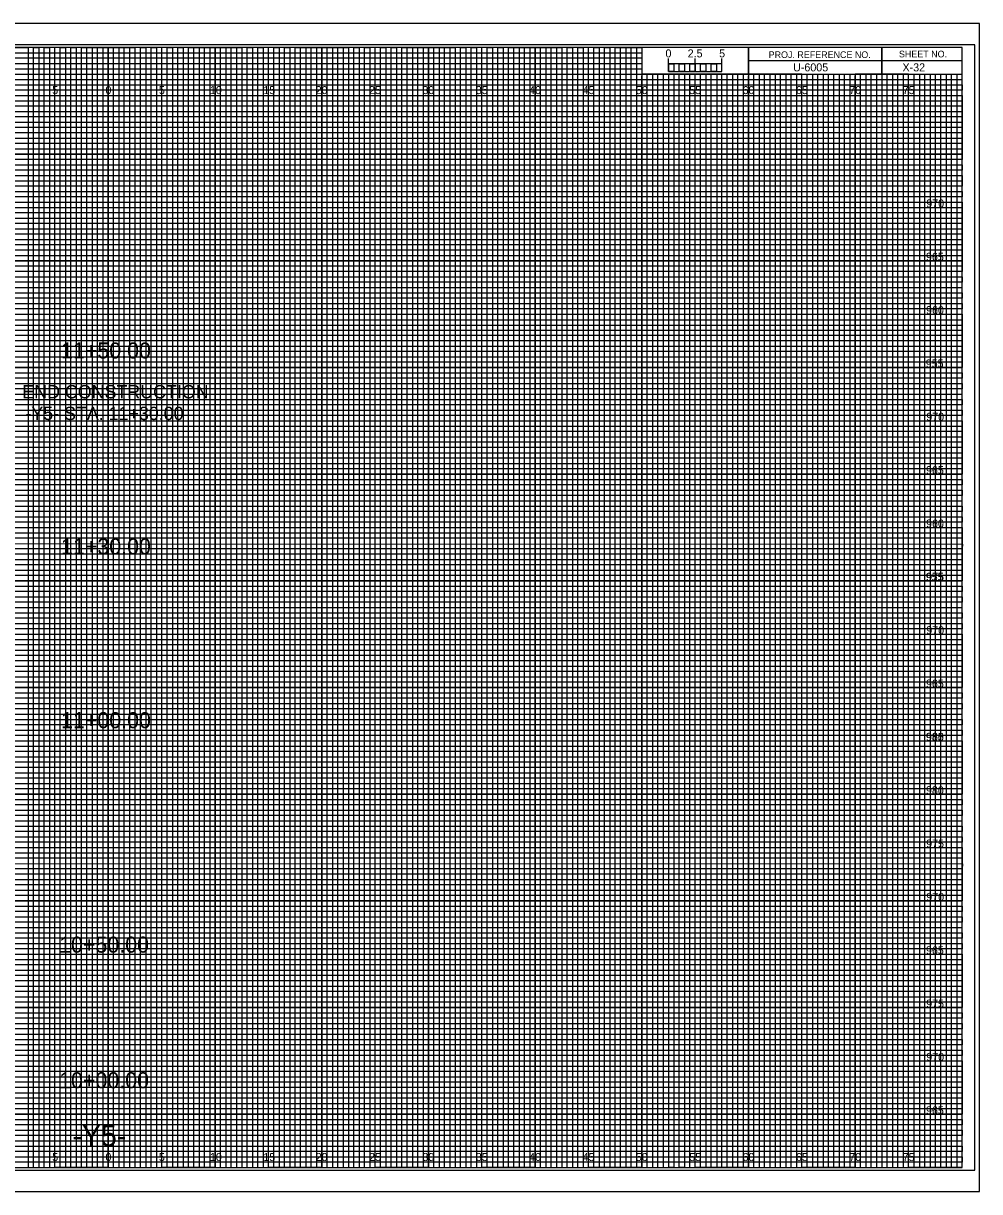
# Model space of a CAD drawing. Extents: x -7 to 162, y -2 to 107.
# Drawn here: x 72 to 161.7, y -2.3 to 107.3 of the extents above; entities that cross this region are included whole.
import ezdxf

# ---------------------------------------------------------------- set-up
doc = ezdxf.new("R2010")
doc.units = 0
for name, color, linetype in [('Prop XS Alignment Label', 7, 'Continuous'), ('Prop XS Bar Scale Labels', 7, 'Continuous'), ('Prop XS Elevation Labels', 7, 'Continuous'), ('Prop XS Label Text', 7, 'Continuous'), ('Prop XS Offset Labels', 7, 'Continuous'), ('Prop XS Project Number', 7, 'Continuous'), ('Prop XS Sheet Number', 7, 'Continuous'), ('Prop XS Station Labels', 7, 'Continuous'), ('Sheet Cross Section CELL', 7, 'Continuous'), ('Sheet Cross Section Grid Major CELL', 7, 'Continuous'), ('Sheet Cross Section Grid Middle CELL', 7, 'Continuous'), ('Sheet Cross Section Grid Minor 1 CELL', 7, 'Continuous'), ('Sheet Cross Section Grid Minor 2 CELL', 7, 'Continuous'), ('Sheet Cross Section Scale CELL', 7, 'Continuous'), ('Sheet Cutting Line CELL', 7, 'Continuous'), ('Sheet DOT Grid CELL', 7, 'Continuous'), ('Sheet Plot Border Inside CELL', 7, 'Continuous'), ('Sheet Plot Border Outside CELL', 7, 'Continuous')]:
    doc.layers.add(name, color=color, linetype=linetype)

msp = doc.modelspace()

# ---------------------------------------------------------------- linework, layer by layer
at = {"layer": 'Sheet Cross Section CELL'}
for p, q in [((152.5, 105), (152.5, 102.5)), ((152.5, 102.5), (152.5, 105)), ((160, 103.75), (140, 103.75)), ((140, 103.75), (140, 102.5)), ((140, 102.5), (160, 102.5))]:
    msp.add_line(p, q, dxfattribs=at)
for points in [[(160, 105), (0, 105), (0, 0), (160, 0)], [(140, 105), (130, 105), (130, 102.52), (140, 102.52)], [(160, 105), (140, 105), (140, 102.5), (160, 102.5)]]:
    msp.add_lwpolyline(points, close=True, dxfattribs=at)
at = {"layer": 'Sheet Cross Section Grid Major CELL'}
for p, q in [((75, 105), (70, 105)), ((75, 0), (75, 105)), ((85, 105), (80, 105)), ((80, 105), (80, 0)), ((85, 0), (85, 105)), ((95, 105), (90, 105)), ((90, 105), (90, 0)), ((95, 0), (95, 105)), ((105, 105), (100, 105)), ((100, 105), (100, 0)), ((105, 0), (105, 105)), ((115, 105), (110, 105)), ((110, 105), (110, 0)), ((115, 0), (115, 105)), ((125, 105), (120, 105)), ((120, 105), (120, 0)), ((125, 0), (125, 105)), ((130, 105), (130, 0)), ((135, 0), (135, 102.5)), ((145, 102.5), (140, 102.5)), ((140, 102.5), (140, 0)), ((145, 0), (145, 102.5)), ((155, 102.5), (150, 102.5)), ((150, 102.5), (150, 0)), ((155, 0), (155, 102.5)), ((80, 0), (75, 0)), ((90, 0), (85, 0)), ((100, 0), (95, 0)), ((110, 0), (105, 0)), ((120, 0), (115, 0)), ((130, 0), (125, 0)), ((140, 0), (135, 0)), ((150, 0), (145, 0)), ((160, 0), (155, 0)), ((160, 0), (160, 0))]:
    msp.add_line(p, q, dxfattribs=at)
for points in [[(0, 100), (160, 100), (160, 95), (0, 95)], [(0, 90), (160, 90), (160, 85), (0, 85)], [(0, 80), (160, 80), (160, 75), (0, 75)], [(0, 70), (160, 70), (160, 65), (0, 65)], [(0, 60), (160, 60), (160, 55), (0, 55)], [(0, 50), (160, 50), (160, 45), (0, 45)], [(0, 40), (160, 40), (160, 35), (0, 35)], [(0, 30), (160, 30), (160, 25), (0, 25)], [(0, 20), (160, 20), (160, 15), (0, 15)], [(0, 10), (160, 10), (160, 5), (0, 5)]]:
    msp.add_lwpolyline(points, dxfattribs=at)
at = {"layer": 'Sheet Cross Section Grid Middle CELL'}
for points in [[(67.5, 105), (72.5, 105), (72.5, 0), (77.5, 0), (77.5, 105), (82.5, 105), (82.5, 0), (87.5, 0), (87.5, 105), (92.5, 105), (92.5, 0), (97.5, 0), (97.5, 105), (102.5, 105), (102.5, 0), (107.5, 0), (107.5, 105), (112.5, 105), (112.5, 0), (117.5, 0), (117.5, 105), (122.5, 105), (122.5, 0), (127.5, 0), (127.5, 105), (129.97, 105), (130, 105), (130, 102.5), (132.5, 102.5), (132.5, 0), (137.5, 0), (137.5, 102.5), (142.5, 102.5), (142.5, 0), (147.5, 0), (147.5, 102.5), (152.5, 102.5), (152.5, 0), (157.5, 0), (157.5, 102.5)], [(0, 102.5), (137.5, 102.5)], [(0, 92.5), (160, 92.5), (160, 97.5), (0, 97.5)], [(0, 82.5), (160, 82.5), (160, 87.5), (0, 87.5)], [(0, 72.5), (160, 72.5), (160, 77.5), (0, 77.5)], [(0, 62.5), (160, 62.5), (160, 67.5), (0, 67.5)], [(0, 52.5), (160, 52.5), (160, 57.5), (0, 57.5)], [(0, 42.5), (160, 42.5), (160, 47.5), (0, 47.5)], [(0, 32.5), (160, 32.5), (160, 37.5), (0, 37.5)], [(0, 22.5), (160, 22.5), (160, 27.5), (0, 27.5)], [(0, 12.5), (160, 12.5), (160, 17.5), (0, 17.5)], [(0, 2.5), (160, 2.5), (160, 7.5), (0, 7.5)]]:
    msp.add_lwpolyline(points, dxfattribs=at)
at = {"layer": 'Sheet Cross Section Grid Minor 1 CELL'}
for p, q in [((0, 104.5), (130, 104.5)), ((130, 104.5), (130, 103.99)), ((130, 103.99), (0, 103.99)), ((0, 103.5), (130, 103.5)), ((130, 102.95), (0, 102.95)), ((130, 103.5), (130, 102.95)), ((0, 102), (160, 102))]:
    msp.add_line(p, q, dxfattribs=at)
for points in [[(0, 101.5), (135, 101.5), (160, 101.5), (160, 101), (0, 101)], [(0, 100.5), (160, 100.5), (160, 99.5), (0, 99.5)], [(0, 99), (160, 99), (160, 98.5), (0, 98.49)], [(0, 98), (160, 98), (160, 97), (0, 97)], [(0, 96.5), (160, 96.5), (160, 96), (0, 96)], [(0, 95.5), (160, 95.5), (160, 94.5), (0, 94.5)], [(0, 94), (160, 94), (160, 93.5), (0, 93.5)], [(0, 93), (160, 93), (160, 92), (0, 92)], [(0, 91.5), (160, 91.5), (160, 91), (0, 91)], [(0, 90.5), (160, 90.5), (160, 89.5), (0, 89.5)], [(0, 89), (160, 89), (160, 88.5), (0, 88.5)], [(0, 88), (160, 88), (160, 86.98), (160, 86.5), (160, 86), (0, 86)], [(0, 87), (160, 87), (160, 86.5), (0, 86.5)], [(0, 85.5), (160, 85.5), (160, 84.5), (0, 84.52)], [(0, 84.52), (160, 84.5), (160, 84), (0, 84)], [(0, 83.5), (160, 83.5), (160, 83), (0, 83)], [(0, 82), (160, 82), (160, 81.5), (0, 81.5)], [(0, 81), (160, 81), (160, 80.5), (0, 80.5)], [(-0.04, 79.45), (160, 79.45), (160, 78.94), (-0.04, 78.94)], [(0, 78.5), (160, 78.5), (160, 78), (0, 78)], [(0, 77), (160, 77), (160, 76.5), (0, 76.5)], [(0, 76), (160, 76), (160, 75.5), (0, 75.5)], [(0, 74.5), (160, 74.5), (160, 74), (0, 74)], [(0, 73.5), (160, 73.5), (160, 73), (0, 73)], [(0, 72), (160, 72), (160, 71.5), (0, 71.5)], [(0, 71), (160, 71), (160, 70.5), (0, 70.5)], [(0, 69.5), (160, 69.5), (160, 68.99), (0, 69)], [(0, 68.5), (160, 68.5), (160, 68), (0, 68)], [(0, 67), (160, 67), (160, 66.5), (0, 66.5)], [(0, 66), (160, 66), (160, 65.5), (0, 65.5)], [(0, 64.5), (160, 64.5), (160, 64), (0, 64)], [(0, 63.5), (160, 63.5), (160, 63), (0, 63)], [(0, 62), (160, 62), (160, 61.5), (0, 61.5)], [(0, 61), (160, 61), (160, 60.5), (0, 60.5)], [(0, 59.5), (160, 59.5), (160, 59), (0, 59)], [(0, 58.5), (160.03, 58.45), (160, 58), (0, 58)], [(0, 57), (160, 57), (160, 56.5), (0, 56.5)], [(0, 56), (160, 56), (160, 55.5), (0, 55.5)], [(0, 54.5), (160, 54.5), (160, 54), (0, 54)], [(0, 53.5), (160, 53.5), (160, 53), (0, 53)], [(0, 52), (160, 52), (160, 51.5), (0, 51.5)], [(0, 51), (160, 51), (160, 50.5), (0, 50.5)], [(0, 49.5), (160, 49.5), (160, 49), (0, 49)], [(0, 48.5), (160, 48.5), (160, 48), (0, 48)], [(0, 47), (160, 47), (160, 46.5), (0, 46.5)], [(0, 46), (160, 46), (160, 45.5), (0, 45.5)], [(0, 44.5), (160, 44.5), (160, 44), (0, 44)], [(0, 43.5), (160, 43.5), (160, 43), (0, 43)], [(0, 42), (160, 42), (160, 41.5), (0, 41.5)], [(0, 41), (160, 41), (160, 40.5), (0, 40.5)], [(0, 39.5), (160, 39.5), (160, 38.99), (0, 39)], [(0, 38.5), (160, 38.5), (160, 38), (0, 38)], [(0, 37), (160, 37), (160, 36.5), (0, 36.5)], [(0, 36), (160, 36), (160, 35.5), (0, 35.5)], [(0, 34.5), (160, 34.5), (160, 34), (0, 34)], [(0, 33.5), (160, 33.5), (160, 33), (0, 33)], [(0, 32), (160, 32), (160, 31.5), (0, 31.5)], [(0, 31), (160, 31), (160, 30.5), (0, 30.5)], [(0, 29.5), (160, 29.5), (160, 29), (0, 29)], [(0, 28.5), (160.03, 28.46), (160, 28), (0, 28)], [(0, 27), (160, 27), (160, 26.5), (0, 26.5)], [(0, 26), (160, 26), (160, 25.5), (0, 25.5)], [(0, 24.5), (160, 24.5), (160, 24), (0, 24)], [(0, 23.5), (160, 23.5), (160, 23), (0, 23)], [(0, 22), (160, 22), (160, 21.5), (0, 21.5)], [(0, 21), (160, 21), (160, 20.5), (0, 20.5)], [(0, 19.5), (160, 19.5), (160, 19), (0, 19)], [(0, 18.5), (160, 18.5), (160, 18), (0, 18)], [(0, 17), (160, 17), (160, 16.5), (0, 16.5)], [(0, 16), (160, 16), (160, 15.5), (0, 15.5)], [(0, 14.5), (160, 14.5), (160, 14), (0, 14)], [(0, 13.5), (160, 13.5), (160, 13), (0, 13)], [(0, 12), (160, 12), (160, 11.5), (0, 11.5)], [(0, 11), (160, 11), (160, 10.5), (0, 10.5)], [(0, 9.5), (160, 9.5), (160, 9), (0, 9)], [(0, 8.5), (160, 8.5), (160, 8), (0, 8)], [(0, 7), (160, 7), (160, 6.5), (0, 6.5)], [(0, 6), (160, 6), (160, 5.5), (0, 5.5)], [(0, 4.5), (160, 4.5), (160, 4), (0, 4)], [(0, 3.5), (160, 3.5), (160, 3), (0, 3)], [(0, 2), (160, 2), (160, 1.5), (0, 1.5)], [(0, 1), (160, 1), (160, 0.5), (0, 0.5)]]:
    msp.add_lwpolyline(points, dxfattribs=at)
at = {"layer": 'Sheet Cross Section Grid Minor 2 CELL'}
for p, q in [((133.5, 102.5), (133, 102.5)), ((133, 102.5), (133, 0)), ((133.5, 0), (133.5, 102.5)), ((134.5, 102.5), (134, 102.5)), ((134, 102.5), (134, 0)), ((134.5, 0), (134.5, 102.5)), ((133, 0), (132.5, 0)), ((134, 0), (133.5, 0))]:
    msp.add_line(p, q, dxfattribs=at)
for points in [[(72.5, 0), (73, 0), (73, 105), (73.5, 105), (73.5, 0)], [(73.5, 0), (74, 0), (74, 105), (74.5, 105), (74.5, 0)], [(75, 0), (75.5, 0), (75.5, 105), (76, 105), (76, 0)], [(76, 0), (76.5, 0), (76.5, 105), (77, 105), (77, 0)], [(77.5, 0), (78, 0), (78, 105), (78.5, 105), (78.5, 0)], [(78.5, 0), (79, 0), (79, 105), (79.5, 105), (79.5, 0)], [(80, 0), (80.5, 0), (80.5, 105), (81, 105), (81, 0)], [(81, 0), (81.5, 0), (81.5, 105), (82, 105), (82, 0)], [(82.5, 0), (83, 0), (83, 105), (83.5, 105), (83.5, 0)], [(83.5, 0), (84, 0), (84, 105), (84.5, 105), (84.5, 0)], [(85, 0), (85.5, 0), (85.5, 105), (86, 105), (86, 0)], [(86, 0), (86.5, 0), (86.5, 105), (87, 105), (87, 0)], [(87.5, 0), (88, 0), (88, 105), (88.5, 105), (88.5, 0)], [(88.5, 0), (89, 0), (89, 105), (89.5, 105), (89.5, 0)], [(90, 0), (90.5, 0), (90.5, 105), (91, 105), (91, 0)], [(91, 0), (91.5, 0), (91.5, 105), (92, 105), (92, 0)], [(92.5, 0), (93, 0), (93, 105), (93.5, 105), (93.5, 0)], [(93.5, 0), (94, 0), (94, 105), (94.5, 105), (94.5, 0)], [(95, 0), (95.5, 0), (95.5, 105), (96, 105), (96, 0)], [(96, 0), (96.5, 0), (96.5, 105), (97, 105), (97, 0)], [(97.5, 0), (98, 0), (98, 105), (98.5, 105), (98.5, 0)], [(98.5, 0), (99, 0), (99, 105), (99.5, 105), (99.5, 0)], [(100, 0), (100.5, 0), (100.5, 105), (101, 105), (101, 0)], [(101, 0), (101.5, 0), (101.5, 105), (102, 105), (102, 0)], [(102.5, 0), (103, 0), (103, 105), (103.5, 105), (103.5, 0)], [(103.5, 0), (104, 0), (104, 105), (104.5, 105), (104.5, 0)], [(105, 0), (105.5, 0), (105.5, 105), (106, 105), (106, 0)], [(106, 0), (106.5, 0), (106.5, 105), (107, 105), (107, 0)], [(107.5, 0), (108, 0), (108, 105), (108.5, 105), (108.5, 0)], [(108.5, 0), (109, 0), (109, 105), (109.5, 105), (109.5, 0)], [(110, 0), (110.5, 0), (110.5, 105), (111, 105), (111, 0)], [(111, 0), (111.5, 0), (111.5, 105), (112, 105), (112, 0)], [(112.5, 0), (113, 0), (113, 105), (113.5, 105), (113.5, 0)], [(113.5, 0), (114, 0), (114, 105), (114.5, 105), (114.5, 0)], [(115, 0), (115.5, 0), (115.5, 105), (116, 105), (116, 0)], [(116, 0), (116.5, 0), (116.5, 105), (117, 105), (117, 0)], [(117.5, 0), (118, 0), (118, 105), (118.5, 105), (118.5, 0)], [(118.5, 0), (119, 0), (119, 105), (119.5, 105), (119.5, 0)], [(120, 0), (120.5, 0), (120.5, 105), (121, 105), (121, 0)], [(121, 0), (121.5, 0), (121.5, 105), (122, 105), (122, 0)], [(122.5, 0), (123, 0), (123, 105), (123.5, 105), (123.5, 0)], [(123.5, 0), (124, 0), (124, 105), (124.5, 105), (124.5, 0)], [(125, 0), (125.5, 0), (125.5, 105), (126, 105), (126, 0)], [(126, 0), (126.5, 0), (126.5, 105), (127, 105), (127, 0)], [(127.5, 0), (128, 0), (128, 105), (128.5, 105), (128.5, 0)], [(128.5, 0), (129, 0), (129, 105), (129.5, 105), (129.5, 0)], [(130, 0), (130.5, 0), (130.5, 102.5), (131.01, 102.5), (131.01, 0)], [(131, 0), (131.5, 0), (131.5, 102.5), (132, 102.5), (132, 0)], [(135, 0), (135.49, 0), (135.49, 102.5), (136, 102.5), (136, 0)], [(136, 0), (136.5, 0), (136.5, 102.5), (137.03, 102.5), (137.03, 0)], [(137.5, 0), (138, 0), (138, 102.5), (138.5, 102.5), (138.5, 0)], [(138.5, 0), (139, 0), (139, 102.5), (139.5, 102.5), (139.5, 0)], [(140, 0), (140.5, 0), (140.5, 102.5), (141, 102.5), (141, 0)], [(141, 0), (141.5, 0), (141.5, 102.5), (142, 102.5), (142, 0)], [(142.5, 0), (143, 0), (143, 102.5), (143.5, 102.5), (143.5, 0)], [(143.5, 0), (144, 0), (144, 102.5), (144.5, 102.5), (144.5, 0)], [(145, 0), (145.5, 0), (145.5, 102.5), (146, 102.5), (146, 0)], [(146, 0), (146.5, 0), (146.5, 102.5), (147, 102.5), (147, 0)], [(147.5, 0), (148, 0), (148, 102.5), (148.5, 102.5), (148.5, 0)], [(148.5, 0), (149, 0), (149, 102.5), (149.5, 102.5), (149.5, 0)], [(150, 0), (150.5, 0), (150.5, 102.5), (151, 102.5), (151, 0)], [(151, 0), (151.5, 0), (151.5, 102.5), (152, 102.5), (152, 0)], [(152.5, 0), (153, 0), (153, 102.5), (153.5, 102.5), (153.5, 0)], [(153.5, 0), (154, 0), (154, 102.5), (154.5, 102.5), (154.5, 0)], [(155, 0), (155.5, 0), (155.5, 102.5), (156, 102.5), (156, 0)], [(156, 0), (156.5, 0), (156.5, 102.5), (157, 102.5), (157, 0)], [(157.5, 0), (158, 0), (158, 102.5), (158.5, 102.5), (158.5, 0)], [(158.5, 0), (159, 0), (159, 102.5), (159.5, 102.5), (159.5, 0)]]:
    msp.add_lwpolyline(points, dxfattribs=at)
at = {"layer": 'Sheet Cross Section Scale CELL'}
for p, q in [((132.5, 102.75), (132.5, 103.95)), ((132.5, 103.45), (132.5, 103.95)), ((135, 102.75), (135, 103.95)), ((137.5, 102.75), (137.5, 103.95)), ((137.5, 103.45), (137.5, 103.95))]:
    msp.add_line(p, q, dxfattribs=at)
for points in [[(137.5, 103.45), (132.5, 103.45), (132.5, 102.75), (137.5, 102.75)], [(132.5, 103.45), (133, 103.45), (133, 102.75), (132.5, 102.75)], [(133.5, 103.45), (134, 103.45), (134, 102.75), (133.5, 102.75)], [(134.5, 103.45), (135, 103.45), (135, 102.75), (134.5, 102.75)], [(135.5, 103.45), (136, 103.45), (136, 102.75), (135.5, 102.75)], [(136.5, 103.45), (137, 103.45), (137, 102.75), (136.5, 102.75)]]:
    msp.add_lwpolyline(points, close=True, dxfattribs=at)
at = {"layer": 'Sheet Cutting Line CELL'}
for p, q in [((161.65, 107.25), (-6.7, 107.25)), ((-6.7, -2.25), (161.65, -2.25))]:
    msp.add_line(p, q, dxfattribs=at)
at = {"layer": 'Sheet DOT Grid CELL'}
for p, q in [((75, 0), (75, 105)), ((80, 0), (80, 105)), ((85, 0), (85, 105)), ((90, 0), (90, 105)), ((95, 0), (95, 105)), ((100, 0), (100, 105)), ((105, 0), (105, 105)), ((110, 0), (110, 105)), ((115, 0), (115, 105)), ((120, 0), (120, 105)), ((125, 0), (125, 105)), ((130, 0), (130, 102.34)), ((135, 0), (135, 102.34)), ((140, 0), (140, 102.34)), ((145, 0), (145, 102.34)), ((150, 0), (150, 102.34)), ((155, 0), (155, 102.34)), ((0, 100), (160, 100)), ((0, 95), (160, 95)), ((0, 90), (160, 90)), ((0, 85), (160, 85)), ((0, 80), (160, 80)), ((0, 75), (160, 75)), ((0, 70), (160, 70)), ((0, 65), (160, 65)), ((0, 60), (160, 60)), ((0, 55), (160, 55)), ((0, 50), (160, 50)), ((0, 45), (160, 45)), ((0, 40), (160, 40)), ((0, 35), (160, 35)), ((0, 30), (160, 30)), ((0, 25), (160, 25)), ((0, 20), (160, 20)), ((0, 15), (160, 15)), ((0, 10), (160, 10)), ((0, 5), (160, 5))]:
    msp.add_line(p, q, dxfattribs=at)
at = {"layer": 'Sheet Plot Border Inside CELL'}
msp.add_lwpolyline([(-5.4, -0.25), (161.2, -0.25), (161.2, 105.25), (-5.4, 105.25)], close=True, dxfattribs=at)
at = {"layer": 'Sheet Plot Border Outside CELL'}
msp.add_lwpolyline([(-6.7, -2.25), (161.65, -2.25), (161.65, 107.25), (-6.7, 107.25)], close=True, dxfattribs=at)

# ---------------------------------------------------------------- texts
at = {"layer": 'Prop XS Alignment Label'}
msp.add_text('-Y5-', height=2, dxfattribs=at).set_placement((76.63, 2))
at = {"layer": 'Prop XS Bar Scale Labels'}
for s, p in [('2.5', (134.29, 104.06)), ('5', (137.24, 104.06))]:
    msp.add_text(s, height=0.75, dxfattribs=at).set_placement(p)
at = {"layer": 'Prop XS Elevation Labels'}
for s, p in [('970', (156.65, 90)), ('965', (156.62, 85)), ('960', (156.63, 80)), ('955', (156.6, 75)), ('970', (156.65, 70)), ('965', (156.62, 65)), ('960', (156.63, 60)), ('955', (156.6, 55)), ('975', (156.64, 55)), ('970', (156.65, 50)), ('965', (156.62, 45)), ('985', (156.61, 40)), ('960', (156.63, 40)), ('980', (156.62, 35)), ('975', (156.64, 30)), ('970', (156.65, 25)), ('965', (156.62, 20)), ('975', (156.64, 15)), ('970', (156.65, 10)), ('965', (156.62, 5))]:
    msp.add_text(s, height=0.75, dxfattribs=at).set_placement(p)
at = {"layer": 'Prop XS Label Text'}
for s, p in [('END CONSTRUCTION', (71.94, 72.1)), ('-Y5- STA. 11+30.00', (72.23, 70.07))]:
    msp.add_text(s, height=1.25, dxfattribs=at).set_placement(p)
at = {"layer": 'Prop XS Offset Labels'}
for s, p in [('5', (74.74, 100.62)), ('0', (79.73, 100.62)), ('0', (79.73, 100.62)), ('5', (84.74, 100.62)), ('10', (89.52, 100.62)), ('15', (94.53, 100.62)), ('20', (99.43, 100.62)), ('25', (104.44, 100.62)), ('30', (109.43, 100.62)), ('35', (114.44, 100.62)), ('40', (119.43, 100.62)), ('45', (124.44, 100.62)), ('50', (129.43, 100.62)), ('55', (134.44, 100.62)), ('60', (139.43, 100.62)), ('65', (144.44, 100.62)), ('70', (149.43, 100.62)), ('75', (154.44, 100.62)), ('5', (74.74, 0.62)), ('0', (79.73, 0.62)), ('0', (79.73, 0.62)), ('5', (84.74, 0.62)), ('10', (89.52, 0.62)), ('15', (94.53, 0.62)), ('20', (99.43, 0.62)), ('25', (104.44, 0.62)), ('30', (109.43, 0.62)), ('35', (114.44, 0.62)), ('40', (119.43, 0.62)), ('45', (124.44, 0.62)), ('50', (129.43, 0.62)), ('55', (134.44, 0.62)), ('60', (139.43, 0.62)), ('65', (144.44, 0.62)), ('70', (149.43, 0.62)), ('75', (154.44, 0.62))]:
    msp.add_text(s, height=0.75, dxfattribs=at).set_placement(p)
at = {"layer": 'Prop XS Project Number'}
msp.add_text('U-6005', height=0.75, dxfattribs=at).set_placement((144.17, 102.75))
at = {"layer": 'Prop XS Sheet Number'}
msp.add_text('X-32', height=0.75, dxfattribs=at).set_placement((154.42, 102.75))
at = {"layer": 'Prop XS Station Labels'}
for s, p in [('11+50.00', (75.57, 75.84)), ('11+30.00', (75.57, 57.48)), ('11+00.00', (75.57, 41.19)), ('10+50.00', (75.39, 20.15)), ('10+00.00', (75.39, 7.44))]:
    msp.add_text(s, height=1.5, dxfattribs=at).set_placement(p)
at = {"layer": 'Sheet Cross Section CELL'}
for s, p in [('PROJ. REFERENCE NO.', (141.88, 104)), ('SHEET NO.', (154.09, 104.06))]:
    msp.add_text(s, height=0.625, dxfattribs=at).set_placement(p)
at = {"layer": 'Sheet Cross Section Scale CELL'}
msp.add_text('0', height=0.75, dxfattribs=at).set_placement((132.21, 104.06))

doc.saveas('drawing.dxf')
